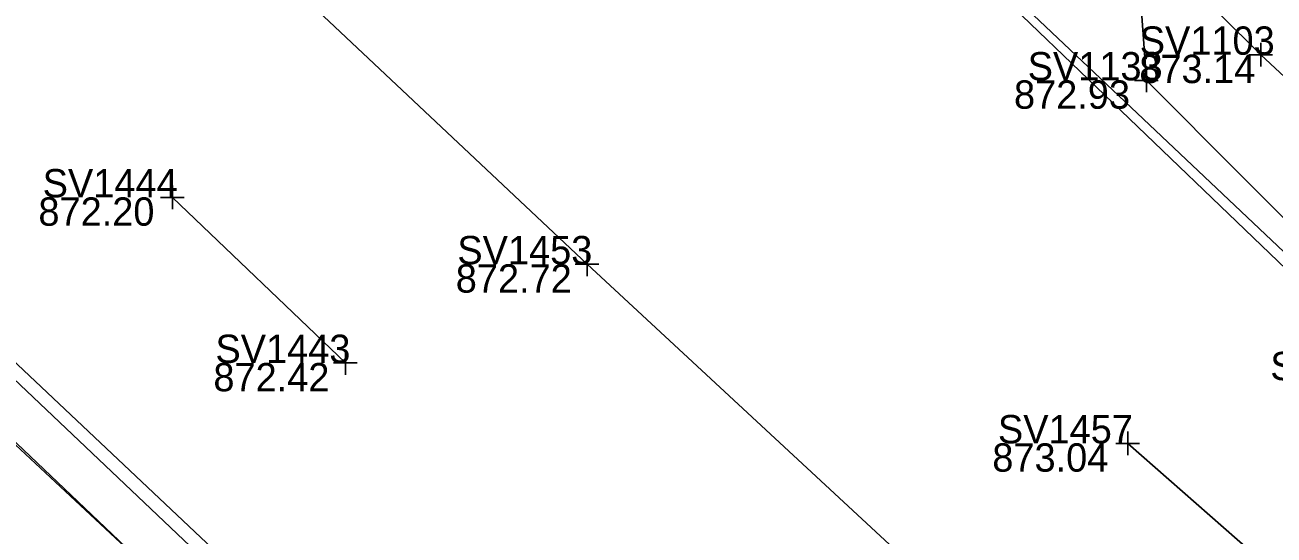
# Model space of a CAD drawing. Extents: x 1480001 to 1480402, y 379235 to 379603.
# Drawn here: x 1480080.5 to 1480133.3, y 379477.1 to 379498.7 of the extents above; entities that cross this region are included whole.
import ezdxf

# ---------------------------------------------------------------- set-up
doc = ezdxf.new("R2010")
doc.units = 0
for name, color, linetype in [('PM_P_CL_Double_Solid', 7, 'Continuous'), ('PM_X_Lane_Line', 7, 'Continuous'), ('PV_X_Curb', 7, 'Continuous'), ('PV_X_Walk', 7, 'Continuous'), ('SV_X_Shot_Marker', 7, 'Continuous'), ('SV_X_Text_Elevation', 7, 'Continuous'), ('SV_X_Text_Name', 7, 'Continuous'), ('UT_X_Water', 7, 'Continuous')]:
    doc.layers.add(name, color=color, linetype=linetype)

msp = doc.modelspace()

# ---------------------------------------------------------------- linework, layer by layer
at = {"layer": 'PM_P_CL_Double_Solid'}
msp.add_lwpolyline([(1480030.312, 379558.368), (1480048.994, 379540.544), (1480068.184, 379522.458), (1480086.697, 379505.162), (1480104.247, 379488.61), (1480122.276, 379471.896), (1480139.96, 379455.601)], dxfattribs=at)
at = {"layer": 'PM_X_Lane_Line'}
for p, q in [((1480094.022, 379484.43), (1480086.704, 379491.442)), ((1480134.548, 379474.499), (1480127.117, 379481.028))]:
    msp.add_line(p, q, dxfattribs=at)
at = {"layer": 'PV_X_Curb'}
for points in [[(1480043.308, 379574.086), (1480051.435, 379566.534), (1480067.64, 379551.083), (1480087.827, 379532.141), (1480105.189, 379515.816), (1480105.937, 379515.205), (1480115.287, 379506.588), (1480116.588, 379505.377), (1480116.999, 379505.563), (1480121.373, 379501.34), (1480121.053, 379501.135), (1480146.64, 379476.909), (1480171.177, 379454.102), (1480173.021, 379452.229), (1480182.175, 379443.675), (1480183.379, 379442.683), (1480186.184, 379440.013), (1480186.975, 379439.363), (1480207.407, 379420.301)], [(1480042.95, 379573.802), (1480051.182, 379566.018), (1480067.383, 379550.834), (1480087.586, 379531.809), (1480105.067, 379515.41), (1480105.589, 379514.887), (1480115.079, 379506.297), (1480116.303, 379505.052), (1480118.53, 379502.967), (1480120.902, 379500.821), (1480138.714, 379483.703), (1480170.84, 379453.681), (1480172.574, 379452.083), (1480181.867, 379443.345), (1480182.839, 379442.217), (1480185.607, 379439.661), (1480186.493, 379438.955), (1480206.919, 379419.855)], [(1480135.19, 379432.332), (1480118.45, 379448.16), (1480110.152, 379455.954), (1480109.273, 379456.61), (1480100.92, 379464.722), (1480096.044, 379469.27), (1480093.779, 379471.437), (1480091.422, 379473.761), (1480089.145, 379475.876), (1480069.411, 379494.504), (1480056.455, 379506.379), (1480055.435, 379507.417), (1480042.302, 379520.019), (1480041.64, 379520.833), (1480030.984, 379530.729), (1480016.059, 379544.67)], [(1480135, 379431.897), (1480118.039, 379447.914), (1480109.91, 379455.647), (1480108.98, 379456.443), (1480100.472, 379464.439), (1480095.645, 379469.163), (1480093.387, 379471.311), (1480093.127, 379470.939), (1480088.623, 379475.041), (1480088.838, 379475.368), (1480068.906, 379494.276), (1480056.264, 379506.212), (1480055.202, 379507.245), (1480042.335, 379519.353), (1480041.39, 379520.138), (1480030.539, 379530.321), (1480016.21, 379543.914)]]:
    msp.add_lwpolyline(points, dxfattribs=at)
at = {"layer": 'PV_X_Walk'}
for points in [[(1480235.613, 379401.335), (1480215.341, 379421.047), (1480197.466, 379437.463), (1480177.803, 379455.97), (1480154.79, 379476.967), (1480132.747, 379497.48), (1480113.376, 379516.728), (1480110.754, 379519.04), (1480109.877, 379518.336), (1480091.944, 379535.267), (1480093.027, 379536.619), (1480090.219, 379539.243), (1480090.463, 379539.725), (1480084.681, 379544.882), (1480083.843, 379544.144), (1480066.818, 379560.524), (1480045.662, 379580.046)], [(1480053.564, 379505.61), (1480071.797, 379488.664), (1480089.369, 379472.273), (1480095.978, 379465.936)]]:
    msp.add_lwpolyline(points, dxfattribs=at)
at = {"layer": 'SV_X_Shot_Marker'}
for p, q in [((1480132.747, 379497.98), (1480132.747, 379496.98)), ((1480132.247, 379497.48), (1480133.247, 379497.48)), ((1480132.747, 379497.48), (1480132.747, 379497.48)), ((1480127.911, 379496.895), (1480127.911, 379495.895)), ((1480127.411, 379496.395), (1480128.411, 379496.395)), ((1480127.911, 379496.395), (1480127.911, 379496.395)), ((1480086.704, 379491.942), (1480086.704, 379490.942)), ((1480086.204, 379491.442), (1480087.204, 379491.442)), ((1480086.704, 379491.442), (1480086.704, 379491.442)), ((1480104.247, 379489.11), (1480104.247, 379488.11)), ((1480103.747, 379488.61), (1480104.747, 379488.61)), ((1480104.247, 379488.61), (1480104.247, 379488.61)), ((1480094.022, 379484.93), (1480094.022, 379483.93)), ((1480093.522, 379484.43), (1480094.522, 379484.43)), ((1480094.022, 379484.43), (1480094.022, 379484.43)), ((1480127.117, 379481.528), (1480127.117, 379480.528)), ((1480126.617, 379481.028), (1480127.617, 379481.028)), ((1480127.117, 379481.028), (1480127.117, 379481.028))]:
    msp.add_line(p, q, dxfattribs=at)
at = {"layer": 'UT_X_Water'}
for points in [[(1480049.152, 379568.017), (1480068.611, 379550.193), (1480086.403, 379533.424), (1480090.024, 379530.079), (1480102.295, 379519.134), (1480111.734, 379511.473), (1480120.332, 379509.136), (1480127.535, 379501.668), (1480127.911, 379496.395), (1480140.166, 379484.084), (1480149.088, 379474.708), (1480164.726, 379459.482), (1480172.622, 379452.503), (1480197.813, 379429.111), (1480212.628, 379415.684), (1480231.592, 379398.237)], [(1480225.088, 379345.601), (1480208.322, 379361.342), (1480207.346, 379362.25), (1480199.528, 379369.768), (1480193.21, 379375.651), (1480182.823, 379385.139), (1480177.927, 379389.525), (1480169.423, 379398.321), (1480161.035, 379406.189), (1480144.924, 379421.019), (1480134.739, 379430.559), (1480121.485, 379441.998), (1480113.085, 379450.369), (1480106.418, 379456.915), (1480094.539, 379467.985), (1480089.15, 379472.551), (1480086.751, 379474.713), (1480073.459, 379487.337), (1480068.123, 379493.187), (1480050.678, 379510.207), (1480044.404, 379515.873)]]:
    msp.add_lwpolyline(points, dxfattribs=at)

# ---------------------------------------------------------------- texts
at = {"layer": 'SV_X_Text_Elevation'}
for s, p in [('873.14', (1480127.608, 379496.28)), ('872.93', (1480122.308, 379495.195)), ('872.20', (1480081.035, 379490.242)), ('872.72', (1480098.691, 379487.41)), ('872.42', (1480088.438, 379483.23)), ('873.04', (1480121.391, 379479.828))]:
    msp.add_text(s, height=1.2, dxfattribs=at).set_placement(p)
at = {"layer": 'SV_X_Text_Name'}
for s, p in [('SV1103', (1480127.627, 379497.48)), ('SV1133', (1480122.886, 379496.395)), ('SV1444', (1480081.215, 379491.442)), ('SV1453', (1480098.758, 379488.61)), ('SV1443', (1480088.524, 379484.43)), ('SV1022', (1480133.15, 379483.703)), ('SV1457', (1480121.628, 379481.028))]:
    msp.add_text(s, height=1.2, dxfattribs=at).set_placement(p)

doc.saveas('drawing.dxf')
